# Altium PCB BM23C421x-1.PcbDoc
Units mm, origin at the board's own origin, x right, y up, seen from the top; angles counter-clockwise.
Board outline 18 x 14 mm, 2 copper layers (Top Layer, Bottom Layer); 17 components, 22 nets, 93 pads, 72 vias.
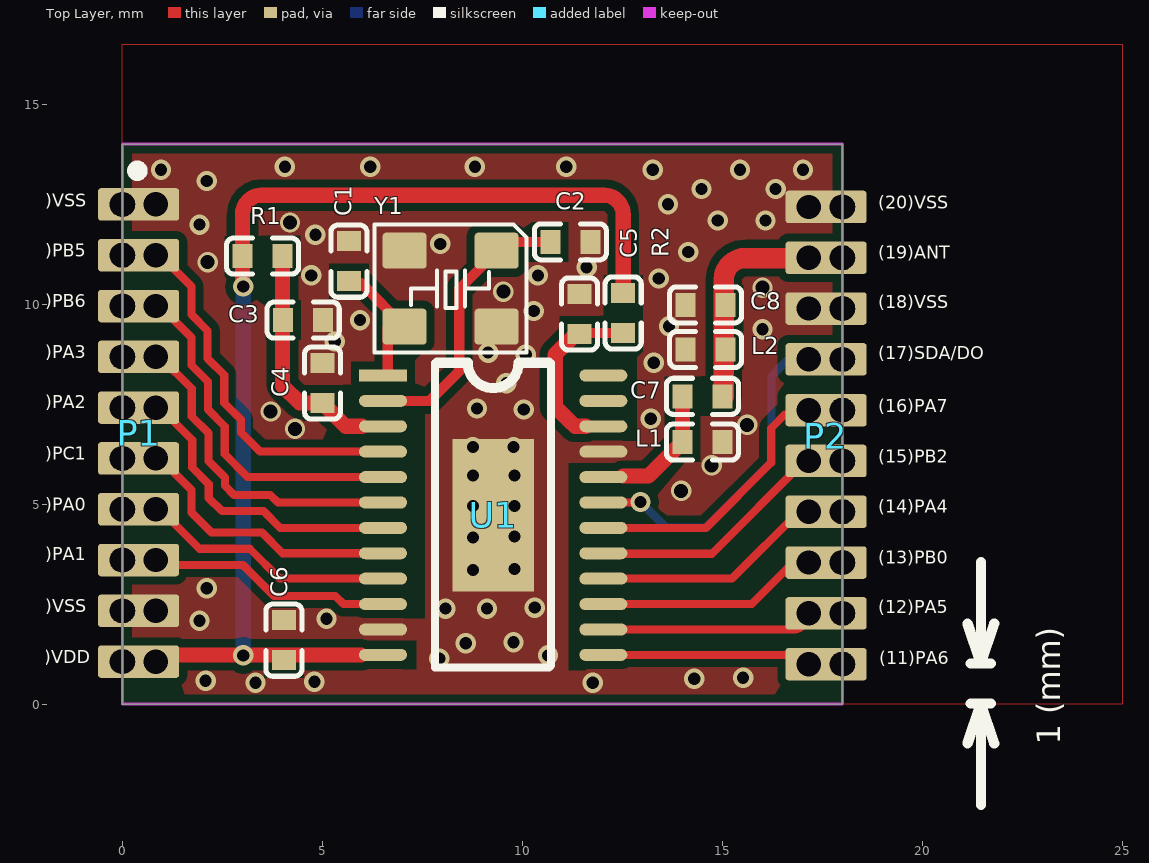
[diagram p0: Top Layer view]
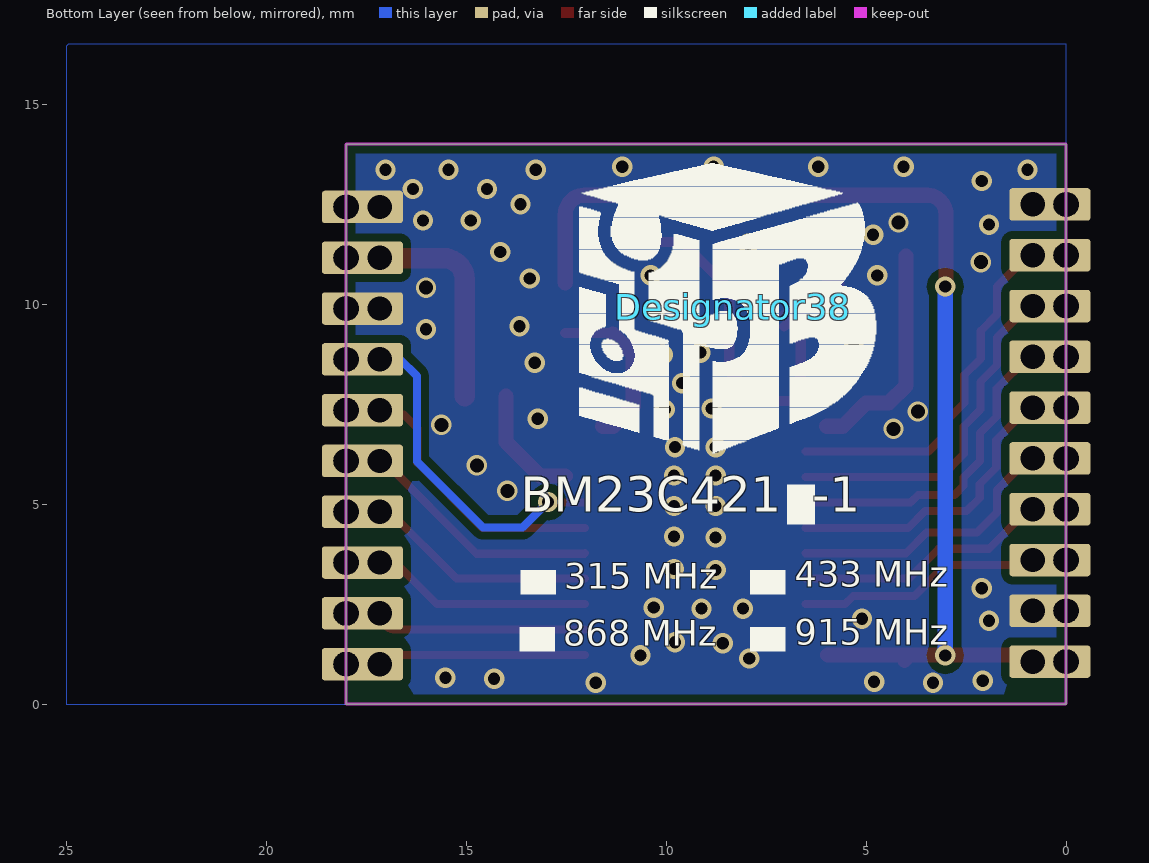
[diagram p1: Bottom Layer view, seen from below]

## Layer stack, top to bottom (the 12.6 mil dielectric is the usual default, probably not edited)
Top Layer: signal copper 0.0356
Dielectric: dielectric 0.32, FR-4, Dk 4.8
Bottom Layer: signal copper 0.0356

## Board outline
0,0 18,0 18,14 0,14 0,0

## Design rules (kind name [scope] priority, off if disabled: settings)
Clearance [All] p1: gap=0.203
PolygonConnect PolygonConnect_1 [IsVia] p1: connectstyle=Direct reliefconductorwidth=0.254 reliefentries=4 polygonreliefangle="90 Angle"
PolygonConnect [All] p2: connectstyle=Direct reliefconductorwidth=0.762 reliefentries=4 polygonreliefangle="90 Angle"
RoutingVias [All] p1: holewidth=0.406 width=0.61 viastyle="Through Hole" minholewidth=0.305 minwidth=0.508 maxholewidth=1.016 maxwidth=1.27
SilkscreenOverComponentPads [IsPad] p1: minsilkscreentomaskgap=0.254
SolderMaskExpansion [All] p1: expansion=0.102
Width [All] p1: maxlimit=1.524 minlimit=0.203 preferedwidth=0.203
27 further rules are at their usual default settings.

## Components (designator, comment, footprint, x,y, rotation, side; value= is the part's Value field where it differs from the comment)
C1 "Cap" 0402C 5.69,10.566 r90 top
C2 "Cap" 0402C 10.693,11.532 r0 top
C3 "Cap" 0402C 4.013,9.576 r0 top
C4 "Cap" 0402C 5.029,7.518 r90 top
C5 "Cap" 0402C 11.455,9.246 r90 top
C6 "Cap" 0402C 4.064,1.092 r90 top
C7 "Cap" 0402C 13.995,7.671 r0 top
C8 "Cap" 0402C 14.072,9.957 r0 top
Designator38 "Comment" logo_1.0 8.331,9.931 r180 bottom
L1 "Inductor" 0402C 15.011,6.579 r180 top
L2 "Inductor" 0402C 14.072,8.839 r0 top
P1 "Header 10" YPK-10PIN_1.27mm#1 0,12.493 r270 top
P2 "Header 10" YPK-10PIN_1.27mm#2 18,1 r90 top
R1 "10R" 0402C 2.997,11.176 r0 top
R2 "10R" 0402C 12.497,10.287 r270 top
U1 "BC66F2342-1" 24SSOP-EP 9.271,4.724 r0 top locked
Y1 "16MHz  12pF" XTAL-SMD3225 9.322,11.354 r180 top

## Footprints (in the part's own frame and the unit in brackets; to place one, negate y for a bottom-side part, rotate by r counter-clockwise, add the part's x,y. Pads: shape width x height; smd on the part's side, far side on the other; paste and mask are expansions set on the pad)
24SSOP-EP [mm]
  rect 2.032x3.81 smd: 0(0,0)
  rect 1.2x0.3 smd: 1(-2.754,3.492)
  oval 1.2x0.3 smd: 2(-2.754,2.857) 3(-2.754,2.222) 4(-2.754,1.587) 5(-2.754,0.953) 6(-2.754,0.318) 7(-2.754,-0.318) 8(-2.754,-0.953) 9(-2.754,-1.587) 10(-2.754,-2.222) 11(-2.754,-2.857) 12(-2.754,-3.492) 13(2.754,-3.492) 14(2.754,-2.857) 15(2.754,-2.222) 16(2.754,-1.587) 17(2.754,-0.953) 18(2.754,-0.318) 19(2.754,0.318) 20(2.754,0.953) 21(2.754,1.587) 22(2.754,2.222) 23(2.754,2.857) 24(2.754,3.492)
  silkscreen extent -1.45,-3.81 1.45,3.81
0402C [mm]
  rect 0.5x0.6 smd: 1(0.008,0.025) 2(1.008,0.025)
  silkscreen extent -0.39,-0.43 1.41,0.48
logo_1.0 [mm]
  silkscreen extent -3.84,-3.66 3.58,3.58
XTAL-SMD3225 [mm]
  rrect20% 1.1x0.9 smd: 1(-0.034,0.016) 2(2.266,0.016) 3(2.266,1.916) 4(-0.034,1.916)
  silkscreen extent -0.78,-0.63 3.02,2.57
YPK-10PIN_1.27mm#1 [mil]
  round 25 hole 24: 1(0,33) 2(50,33) 3(100,33) 4(150,33) 5(200,33) 6(250,33) 7(300,33) 8(350,33) 9(400,33) 10(450,33)
  rrect20% 32x80 hole 24 slot 25 at 90 deg copper offset 0,16: 1(0,0) 2(50,0) 3(100,0) 4(150,0) 5(200,0) 6(250,0) 7(300,0) 8(350,0) 9(400,0) 10(450,0)
YPK-10PIN_1.27mm#2 [mil]
  round 25 hole 24: 11(0,33) 12(50,33) 13(100,33) 14(150,33) 15(200,33) 16(250,33) 17(300,33) 18(350,33) 19(400,33) 20(450,33)
  rrect20% 32x80 hole 24 slot 25 at 90 deg copper offset 0,16: 11(0,0) 12(50,0) 13(100,0) 14(150,0) 15(200,0) 16(250,0) 17(300,0) 18(350,0) 19(400,0) 20(450,0)

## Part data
C1 C2 C3 C4 C5 C6 C7 C8: "Capacitor"
P1 P2: "Header, 10-Pin"
R1 R2: library part RES1
U1: library part BC66F2342
Y1: library part XTAL, "Crystal Oscillator"

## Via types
v1: diameter 0.508, hole 0.305, Top Layer to Bottom Layer, tented both sides, 63 vias
v2: diameter 0.508, hole 0.35, Top Layer to Bottom Layer, tented both sides, 9 vias

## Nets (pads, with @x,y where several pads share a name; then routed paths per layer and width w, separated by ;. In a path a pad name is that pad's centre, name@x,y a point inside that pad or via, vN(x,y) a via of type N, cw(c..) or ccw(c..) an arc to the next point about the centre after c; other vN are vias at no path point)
ANT: C7.2 C8.2 L2.2 P2.19 | length 5.4
  Top Layer w0.508: C7.2@15.037,7.696 15.037,10.617 cw(c15.57,10.617) 15.57,11.151 17.162,11.151 P2.19@17.162,11.16
NetC1_1: C1.1 U1.1 Y1.3 | length 3.3
  Top Layer w0.254: C1.1@5.664,10.524 5.97,10.524 Y1.3 ; U1.1@6.634,8.204 Y1.3@6.634,9.399 ; Y1.3@6.801,9.743 Y1.3@7.056,9.743
NetC2_1: C2.1 U1.2 Y1.1 | length 7
  Top Layer w0.254: U1.2 7.683,7.582 8.425,8.323 8.425,10.38 Y1.1@9.356,11.311 ; Y1.1 9.575,11.557 C2.1
NetC5_1: C5.1 R2.2 U1.22 | length 4.2
  Top Layer w0.254: C5.1@11.336,9.254 C5.1 11.455,9.279 R2.2
  Top Layer w0.381: C5.1@11.336,9.254 10.82,8.738 10.82,7.442 10.944,7.318 11.192,7.071 11.316,6.947 U1.22@11.582,6.947
NetC7_1: C7.1 L1.2 U1.20 | length 3
  Top Layer w0.381: U1.20@12.522,5.702 13.153,5.702 L1.2 C7.1
PA0: P1.7 U1.9 | length 7.2
  Top Layer w0.203: P1.7@0,4.873 0.838,4.873 0.942,4.873 1.929,3.886 3.184,3.886 3.934,3.137 U1.9
PA1: P1.8 U1.10 | length 7
  Top Layer w0.203: P1.8@0,3.603 0.838,3.603 0.961,3.48 3.016,3.48 3.79,2.706 5.323,2.706 5.527,2.502 U1.10
PA2: P1.5 U1.7 | length 8.4
  Top Layer w0.203: P1.5@0,7.413 0.838,7.413 0.942,7.413 1.747,6.608 1.747,5.913 2.159,5.501 2.159,5.156 2.489,4.826 3.529,4.826 3.948,4.407 U1.7
PA3: P1.4 U1.6 | length 9
  Top Layer w0.203: P1.4@0,8.683 0.838,8.683 0.942,8.683 1.734,7.891 1.734,7.195 2.154,6.776 2.154,6.081 2.565,5.669 2.565,5.461 2.794,5.232 3.698,5.232 3.888,5.042 U1.6
PA4: P2.14 U1.16 | length 6.8
  Top Layer w0.203: U1.16 15.24,3.137 16.913,4.81 17.162,4.81 18,4.81 P2.14@18.162,4.81
PA5: P2.12 U1.14 | length 7.5
  Top Layer w0.203: U1.14 16.759,1.867 ccw(c16.759,2.27) P2.12@17.162,2.27 ; P2.12@16.987,2.095 ccw(c16.987,2.27) P2.12@17.162,2.27 ; P2.12@18.162,2.27 18,2.27 P2.12@17.162,2.27
  Bottom Layer w0.203: P2.12@17.162,2.27 P2.12@18,2.27
PA6: P2.11 U1.13 | length 6.1
  Top Layer w0.203: U1.13 16.93,1.232 cw(c16.93,1) 17.162,1 P2.11@18,1
PA7: P2.16 U1.18 | length 8.7
  Top Layer w0.203: U1.18 14.592,4.407 16.222,6.037 16.222,6.898 16.561,7.237 17.049,7.237 17.162,7.35 18,7.35 P2.16@18.162,7.35
  Bottom Layer w0.203: P2.16@17.162,7.35 P2.16@18,7.35
PB0: P2.13 U1.15 | length 6.6
  Top Layer w0.203: U1.15 15.735,2.502 16.773,3.54 17.162,3.54 18,3.54 P2.13@18.162,3.54
PB2: P2.15 U1.17 | length 7
  Top Layer w0.203: U1.17 12.038,3.759 14.737,3.759 P2.15@17.058,6.08 ; P2.15@17.002,6.08 P2.15@17.058,6.08 ; P2.15@18,6.08 17.162,6.08 P2.15@17.058,6.08
PB5: P1.2 U1.4 | length 9.1
  Top Layer w0.203: P1.2@0.838,11.223 0.942,11.223 1.727,10.438 1.727,9.743 2.134,9.336 2.134,8.641 2.547,8.227 2.547,7.532 2.966,7.113 2.966,6.787 3.442,6.312 U1.4
PB6: P1.3 U1.5 | length 9.7
  Top Layer w0.203: P1.3@0,9.953 0.838,9.953 P1.3@0.942,9.953 ; P1.3@1.096,9.953 P1.3@0.942,9.953 ; U1.5 3.133,5.677 2.56,6.249 2.56,6.945 2.141,7.364 2.141,8.059 1.727,8.473 1.727,9.168 P1.3@0.942,9.953
PC1: P1.6 U1.8 | length 7.8
  Top Layer w0.203: P1.6@0,6.143 0.838,6.143 0.942,6.143 1.727,5.358 1.727,4.791 2.226,4.293 3.488,4.293 4.009,3.772 U1.8
RFDVDD: C3.1 C4.1 R1.2 U1.3 | length 5.8
  Top Layer w0.381: R1.2 4.005,7.958 ; 4.127,7.836 4.005,7.958 ; U1.3@5.994,6.947 5.583,6.947 C4.1 4.437,7.526 4.005,7.958
SDA/DO: P2.17 U1.19 | length 10.2
  Top Layer w0.203: U1.19 12.941,5.042 v1(12.954,5.055) ; P2.17@16.9,8.62 17.162,8.62 18,8.62 P2.17@18.162,8.62
  Bottom Layer w0.203: v1(12.954,5.055) 13.589,4.42 ; 13.665,4.42 13.589,4.42 ; P2.17@17.657,8.62 17.162,8.62 16.646,8.62 16.231,8.204 16.231,6.071 14.58,4.42 13.589,4.42
VDD: C6.1 P1.10 R1.1 R2.1 U1.12 | length 29
  Top Layer w0.381: P1.10@0,1.063 0.838,1.063 1.007,1.232 C6.1@3.907,1.232 ; v1(3.023,10.439) 3.005,10.439 R1.1 3.005,12.251 cw(c3.48,12.251) 3.48,12.725 12.04,12.725 cw(c12.04,12.243) 12.522,12.243 12.522,10.533 ; C6.1 C6.1@3.907,1.232 ; U1.12@5.969,1.232 C6.1@3.907,1.232
  Bottom Layer w0.381: v1@3.023,1.232 v1(3.023,10.439)
  other v1: 3.023,1.219
VSS: C1.2 C2.2 C3.2 C4.2 C5.2 C6.2 C8.1 L1.1 L2.1 P1.1 P1.9 P2.18 P2.20 U1.0 U1.11 U1.21 Y1.2 Y1.4 | length 3.4
  Top Layer w0.305: P1.1@0,12.493 P1.1@0.838,12.493
  Top Layer w0.508: P1.9@0,2.333 P1.9@0.838,2.333 ; P2.18@17.162,9.89 P2.18@18,9.89 ; P2.20@17.162,12.43 P2.20@18,12.43
  other v1: 3.327,0.533 11.76,0.533 4.801,0.559 2.083,0.584 14.3,0.635 15.519,0.66 7.925,1.143 10.643,1.219 8.585,1.524 9.779,1.549 1.93,2.083 5.105,2.134 8.077,2.388 9.119,2.388 10.312,2.413 2.108,2.896 8.763,3.353 9.804,3.378 8.763,4.166 9.804,4.191 8.763,4.953 9.804,4.953 8.763,5.715 9.804,5.715 8.763,6.426 9.779,6.426 13.208,7.137 10.033,7.366 8.865,7.391 9.601,8.026 13.284,8.534 10.084,8.738 9.144,8.788 5.309,9.068 16.002,9.373 13.665,9.449 5.944,9.601 10.287,9.83 13.411,10.643 4.724,10.719 10.389,10.719 11.608,10.922 14.148,11.303 7.95,11.506 4.826,11.735 1.93,11.989 14.884,12.09 16.078,12.09 13.64,12.497 14.478,12.878 16.332,12.878 2.108,13.081 0.965,13.36 13.259,13.36 15.443,13.36 17.018,13.36 4.064,13.437 6.198,13.437 8.814,13.437 11.1,13.437
  other v2: 13.97,5.334 14.732,5.969 4.318,6.883 15.621,6.985 3.708,7.315 9.525,10.312 16.002,10.414 2.134,11.049 4.191,12.04
pads on no net: U1.23 U1.24

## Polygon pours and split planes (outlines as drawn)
VSS on Bottom Layer "Bottom Layer-No Net" (solid, shelved, pour order 16): 0,0 0,16.5 24.917,16.5 cw(c24.917,16.417) 25,16.417 25,0 0,0
VSS on Top Layer "Bottom Layer-No Net" (solid, shelved, pour order 14): 0,0 0,16.5 25,16.5 25,0 0,0
VSS on Bottom Layer "Bottom Layer-No Net" (solid, remove dead copper, pour order 6): 0,0 0,14 18,14 18,0 0,0
VSS on Top Layer "Bottom Layer-No Net" (solid, remove dead copper, pour order 5): 0,0 0,14 0.081,13.919 18,13.919 18,0 0,0

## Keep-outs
Keep-Out Layer:
  the board outline again, w0.076

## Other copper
Top Layer:
  pour cut-out: 7.569,7.239 7.569,2.134 7.036,2.134 6.985,2.184 6.985,7.239 7.534,7.239 7.54,7.245
  pour cut-out: 12.497,8.611 12.878,8.611 12.878,6.579 12.497,6.579 12.495,6.58 12.495,8.573
  pour cut-out: 11.575,6.037 11.159,6.037 11.151,6.045 11.151,0.838 11.582,0.838 11.575,0.846
  pour cut-out: 7.01,1.6 7.366,1.6 7.366,0.864 7.01,0.864

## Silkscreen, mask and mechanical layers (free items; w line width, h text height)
Top Overlay:
  circle w0.254: c0.378,13.335 r0.13
  lines w0.254: 21.13,-0.984 21.463,0.016 ; 21.13,2.016 21.463,1.016 ; 21.209,0.016 21.717,0.016 ; 21.209,1.016 21.717,1.016 ; 21.463,-2.524 21.463,0.016 ; 21.463,3.556 21.463,1.016 ; 21.796,-0.984 21.463,0.016 ; 21.796,2.016 21.463,1.016
  text "(1)VSS" at -2.388,12.319 h0.55
  text "(20)VSS" at 18.898,12.268 h0.55
  text "(2)PB5" at -2.388,11.074 h0.55
  text "(19)ANT" at 18.898,11.024 h0.55
  text "(3)PB6" at -2.388,9.804 h0.55
  text "(18)VSS" at 18.898,9.779 h0.55
  text "(4)PA3" at -2.388,8.534 h0.55
  text "(17)SDA/DO" at 18.898,8.509 h0.55
  text "(5)PA2" at -2.388,7.29 h0.55
  text "(16)PA7" at 18.898,7.188 h0.55
  text "(6)PC1" at -2.388,5.994 h0.55
  text "(15)PB2" at 18.898,5.918 h0.55
  text "(7)PA0" at -2.388,4.724 h0.55
  text "(14)PA4" at 18.898,4.674 h0.55
  text "(8)PA1" at -2.388,3.48 h0.55
  text "(13)PB0" at 18.898,3.404 h0.55
  text "(9)VSS" at -2.388,2.184 h0.55
  text "(12)PA5" at 18.898,2.159 h0.55
  text "(10)VDD" at -2.692,0.914 h0.55
  text "(11)PA6" at 18.923,0.889 h0.55
  text "1 (mm)" at 23.651,-1.018 h1 r90
Bottom Overlay:
  region: 6.274,5.486 6.274,4.496 6.985,4.496 6.985,5.486
  region: 13.64,3.353 12.751,3.353 12.751,2.743 13.64,2.743
  region: 13.665,1.93 12.776,1.93 12.776,1.321 13.665,1.321
  region: 7.899,3.353 7.01,3.353 7.01,2.743 7.899,2.743
  region: 7.899,1.93 7.01,1.93 7.01,1.321 7.899,1.321
  text "BM23C421  -1" at 13.64,4.521 h1.5
  text "433 MHz" at 6.782,2.718 h1.1
  text "315 MHz" at 12.548,2.667 h1.1
  text "915 MHz" at 6.782,1.27 h1.1
  text "868 MHz" at 12.573,1.245 h1.1

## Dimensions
0,0 to 0,14 on Top Overlay
22.784,11.557 to 22.835,10.744 on Top Overlay
-3.023,4.877 to -3.023,6.147 on Top Overlay
1.422,-0.356 to 0,1.063 on Top Overlay
0,14 to 18,14 on Top Overlay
